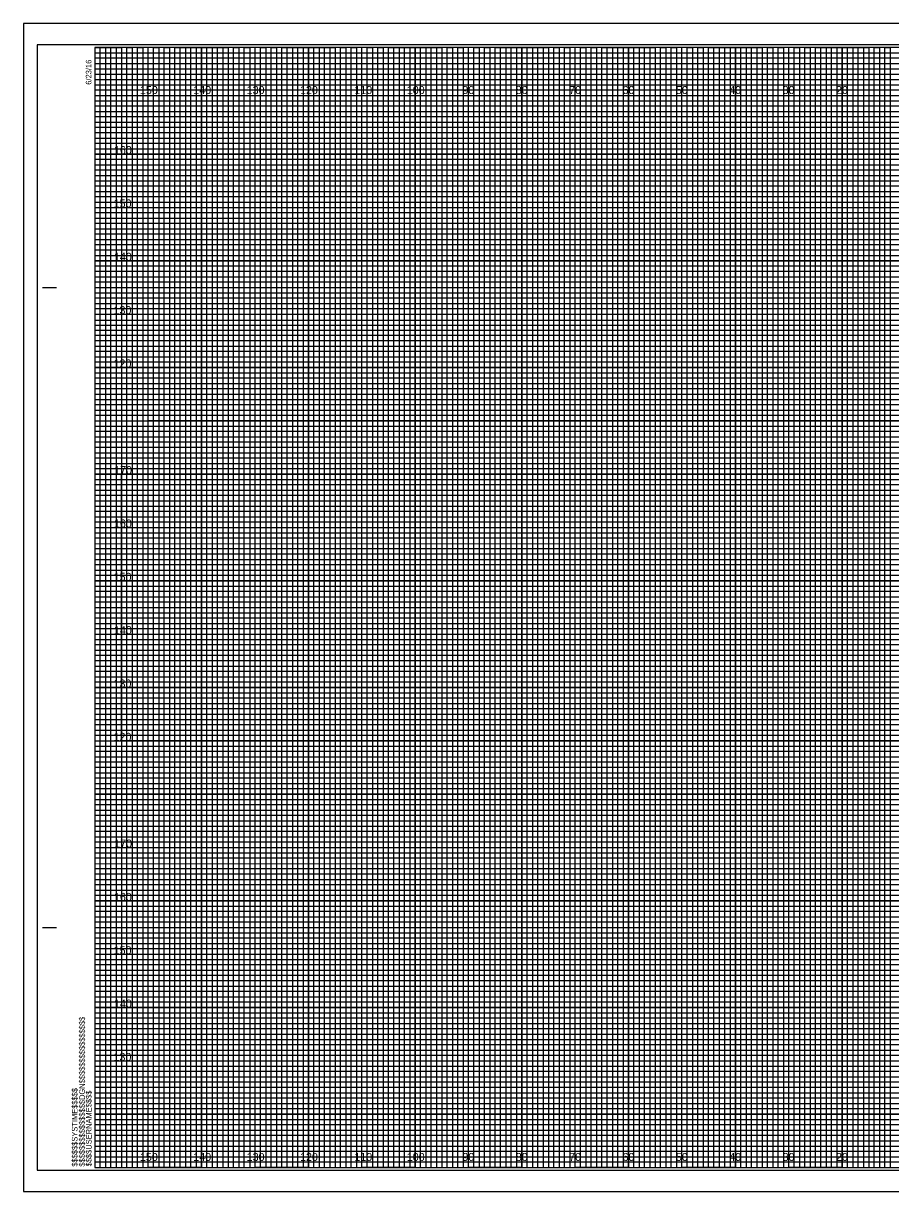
# Model space of a CAD drawing. Extents: x -13 to 323, y -5 to 3294.
# Drawn here: x -13.4 to 149.1, y 2415.5 to 2634.5 of the extents above; entities that cross this region are included whole.
import ezdxf

# ---------------------------------------------------------------- set-up
doc = ezdxf.new("R2010")
doc.units = 0
for name, color, linetype in [('Prop XS Elevation Labels', 7, 'Continuous'), ('Prop XS Offset Labels', 7, 'Continuous'), ('Scratch_Level_0', 7, 'Continuous'), ('Sheet Cross Section CELL', 7, 'Continuous'), ('Sheet Cross Section Grid Major CELL', 7, 'Continuous'), ('Sheet Cross Section Grid Middle CELL', 7, 'Continuous'), ('Sheet Cross Section Grid Minor 1 CELL', 7, 'Continuous'), ('Sheet Cross Section Grid Minor 2 CELL', 7, 'Continuous'), ('Sheet Cutting Line CELL', 7, 'Continuous'), ('Sheet DOT Grid CELL', 7, 'Continuous'), ('Sheet Plot Border Inside CELL', 7, 'Continuous'), ('Sheet Plot Border Outside CELL', 7, 'Continuous')]:
    doc.layers.add(name, color=color, linetype=linetype)

msp = doc.modelspace()

# ---------------------------------------------------------------- linework, layer by layer
at = {"layer": 'Scratch_Level_0'}
for points in [[(10, 2610), (310, 2610), (310, 2560), (10, 2560)], [(5, 2550), (310, 2550), (310, 2500), (5, 2500)], [(10, 2480), (310, 2480), (310, 2430), (10, 2430)]]:
    msp.add_lwpolyline(points, close=True, dxfattribs=at)
at = {"layer": 'Sheet Cross Section CELL'}
for p, q in [((-9.8, 2585), (-7.3, 2585)), ((-9.7, 2585), (-7.2, 2585)), ((-9.8, 2465), (-7.3, 2465)), ((-9.7, 2465), (-7.2, 2465)), ((0, 2420), (0, 2420)), ((0, 2420), (0, 2420)), ((0, 2420), (0, 2420)), ((0, 2420), (0, 2420)), ((0, 2420), (0, 2420)), ((0, 2420), (0, 2420)), ((0, 2420), (0, 2420))]:
    msp.add_line(p, q, dxfattribs=at)
msp.add_lwpolyline([(320, 2630), (0, 2630), (0, 2420), (320, 2420)], close=True, dxfattribs=at)
at = {"layer": 'Sheet Cross Section Grid Major CELL'}
for p, q in [((10, 2630), (0, 2630)), ((10, 2420), (10, 2630)), ((30, 2630), (20, 2630)), ((20, 2630), (20, 2420)), ((30, 2420), (30, 2630)), ((50, 2630), (40, 2630)), ((40, 2630), (40, 2420)), ((50, 2420), (50, 2630)), ((70, 2630), (60, 2630)), ((60, 2630), (60, 2420)), ((70, 2420), (70, 2630)), ((90, 2630), (80, 2630)), ((80, 2630), (80, 2420)), ((90, 2420), (90, 2630)), ((110, 2630), (100, 2630)), ((100, 2630), (100, 2420)), ((110, 2420), (110, 2630)), ((130, 2630), (120, 2630)), ((120, 2630), (120, 2420)), ((130, 2420), (130, 2630)), ((150, 2630), (140, 2630)), ((140, 2630), (140, 2420)), ((20, 2420), (10, 2420)), ((40, 2420), (30, 2420)), ((60, 2420), (50, 2420)), ((80, 2420), (70, 2420)), ((100, 2420), (90, 2420)), ((120, 2420), (110, 2420)), ((140, 2420), (130, 2420))]:
    msp.add_line(p, q, dxfattribs=at)
for points in [[(0, 2620), (320, 2620), (320, 2610), (0, 2610)], [(0, 2600), (320, 2600), (320, 2590), (0, 2590)], [(0, 2580), (320, 2580), (320, 2570), (0, 2570)], [(0, 2560), (320, 2560), (320, 2550), (0, 2550)], [(0, 2540), (320, 2540), (320, 2530), (0, 2530)], [(0, 2520), (320, 2520), (320, 2510), (0, 2510)], [(0, 2500), (320, 2500), (320, 2490), (0, 2490)], [(0, 2480), (320, 2480), (320, 2470), (0, 2470)], [(0, 2460), (320, 2460), (320, 2450), (0, 2450)], [(0, 2440), (320, 2440), (320, 2430), (0, 2430)]]:
    msp.add_lwpolyline(points, dxfattribs=at)
at = {"layer": 'Sheet Cross Section Grid Middle CELL'}
for points in [[(0, 2630), (5, 2630), (5, 2420), (15, 2420), (15, 2630), (25, 2630), (25, 2420), (35, 2420), (35, 2630), (45, 2630), (45, 2420), (55, 2420), (55, 2630), (65, 2630), (65, 2420), (75, 2420), (75, 2630), (85, 2630), (85, 2420), (95, 2420), (95, 2630), (105, 2630), (105, 2420), (115, 2420), (115, 2630), (125, 2630), (125, 2420), (135, 2420), (135, 2630), (145, 2630), (145, 2420), (155, 2420)], [(0, 2625), (275, 2625)], [(0, 2605), (320, 2605), (320, 2615), (0, 2615)], [(0, 2585), (320, 2585), (320, 2595), (0, 2595)], [(0, 2565), (320, 2565), (320, 2575), (0, 2575)], [(0, 2545), (320, 2545), (320, 2555), (0, 2555)], [(0, 2525), (320, 2525), (320, 2535), (0, 2535)], [(0, 2505), (320, 2505), (320, 2515), (0, 2515)], [(0, 2485), (320, 2485), (320, 2495), (0, 2495)], [(0, 2465), (320, 2465), (320, 2475), (0, 2475)], [(0, 2445), (320, 2445), (320, 2455), (0, 2455)], [(0, 2425), (320, 2425), (320, 2435), (0, 2435)]]:
    msp.add_lwpolyline(points, dxfattribs=at)
at = {"layer": 'Sheet Cross Section Grid Minor 1 CELL'}
for p, q in [((0, 2629), (260, 2629)), ((260, 2627.98), (0, 2627.98)), ((0, 2627.98), (0, 2627)), ((0, 2627), (260, 2627)), ((260, 2625.89), (0, 2625.89)), ((0, 2625.89), (0, 2624)), ((0, 2624), (320, 2624))]:
    msp.add_line(p, q, dxfattribs=at)
for points in [[(0, 2623), (270, 2623), (320, 2623), (320, 2622), (0, 2622)], [(0, 2621), (320, 2621), (320, 2619), (0, 2619)], [(0, 2618), (320, 2618), (320, 2617), (0, 2616.98)], [(0, 2616), (320, 2616), (320, 2614), (0, 2614)], [(0, 2613), (320, 2613), (320, 2612), (0, 2612)], [(0, 2611), (320, 2611), (320, 2609), (0, 2609)], [(0, 2608), (320, 2608), (320, 2607), (0, 2607)], [(0, 2606), (320, 2606), (320, 2604), (0, 2604)], [(0, 2603), (320, 2603), (320, 2602), (0, 2602)], [(0, 2601), (320, 2601), (320, 2599), (0, 2599)], [(0, 2598), (320, 2598), (320, 2597), (0, 2597)], [(0, 2596), (320, 2596), (320, 2593.95), (320, 2593), (320, 2592), (0, 2592)], [(0, 2594), (320, 2594), (320, 2593), (0, 2593)], [(0, 2591), (320, 2591), (320, 2589), (0, 2589.03)], [(0, 2589.03), (320, 2589), (320, 2588), (0, 2588)], [(0, 2587), (320, 2587), (320, 2586), (0, 2586)], [(0, 2584), (320, 2584), (320, 2583), (0, 2583)], [(0, 2582), (320, 2582), (320, 2581), (0, 2581)], [(-0.07, 2578.89), (320, 2578.89), (320, 2577.88), (-0.07, 2577.88)], [(0, 2577), (320, 2577), (320, 2576), (0, 2576)], [(0, 2574), (320, 2574), (320, 2573), (0, 2573)], [(0, 2572), (320, 2572), (320, 2571), (0, 2571)], [(0, 2569), (320, 2569), (320, 2568), (0, 2568)], [(0, 2567), (320, 2567), (320, 2566), (0, 2566)], [(0, 2564), (320, 2564), (320, 2563), (0, 2563)], [(0, 2562), (320, 2562), (320, 2561), (0, 2561)], [(0, 2559), (320, 2559), (319.99, 2557.98), (0, 2558)], [(0, 2557), (320, 2557), (320, 2556), (0, 2556)], [(0, 2554), (320, 2554), (320, 2553), (0, 2553)], [(0, 2552), (320, 2552), (320, 2551), (0, 2551)], [(0, 2549), (320, 2549), (320, 2548), (0, 2548)], [(0, 2547), (320, 2547), (320, 2546), (0, 2546)], [(0, 2544), (320, 2544), (320, 2543), (0, 2543)], [(0, 2542), (320, 2542), (320, 2541), (0, 2541)], [(0, 2539), (320, 2539), (320, 2538), (0, 2538)], [(0, 2536.99), (320.07, 2536.91), (320, 2536), (0, 2536)], [(0, 2534), (320, 2534), (320, 2533), (0, 2533)], [(0, 2532), (320, 2532), (320, 2531), (0, 2531)], [(0, 2529), (320, 2529), (320, 2528), (0, 2528)], [(0, 2527), (320, 2527), (320, 2526), (0, 2526)], [(0, 2524), (320, 2524), (320, 2523), (0, 2523)], [(0, 2522), (320, 2522), (320, 2521), (0, 2521)], [(0, 2519), (320, 2519), (320, 2518), (0, 2518)], [(0, 2517), (320, 2517), (320, 2516), (0, 2516)], [(0, 2514), (320, 2514), (320, 2513), (0, 2513)], [(0, 2512), (320, 2512), (320, 2511), (0, 2511)], [(0, 2509), (320, 2509), (320, 2508), (0, 2508)], [(0, 2507), (320, 2507), (320, 2506), (0, 2506)], [(0, 2504), (320, 2504), (320, 2503), (0, 2503)], [(0, 2502), (320, 2502), (320, 2501), (0, 2501)], [(0, 2499), (320, 2499), (319.99, 2497.98), (0, 2498)], [(0, 2497), (320, 2497), (320, 2496), (0, 2496)], [(0, 2494), (320, 2494), (320, 2493), (0, 2493)], [(0, 2492), (320, 2492), (320, 2491), (0, 2491)], [(0, 2489), (320, 2489), (320, 2488), (0, 2488)], [(0, 2487), (320, 2487), (320, 2486), (0, 2486)], [(0, 2484), (320, 2484), (320, 2483), (0, 2483)], [(0, 2482), (320, 2482), (320, 2481), (0, 2481)], [(0, 2479), (320, 2479), (320, 2478), (0, 2478)], [(0, 2476.99), (320.07, 2476.91), (320, 2476), (0, 2476)], [(0, 2474), (320, 2474), (320, 2473), (0, 2473)], [(0, 2472), (320, 2472), (320, 2471), (0, 2471)], [(0, 2469), (320, 2469), (320, 2468), (0, 2468)], [(0, 2467), (320, 2467), (320, 2466), (0, 2466)], [(0, 2464), (320, 2464), (320, 2463), (0, 2463)], [(0, 2462), (320, 2462), (320, 2461), (0, 2461)], [(0, 2459), (320, 2459), (320, 2458), (0, 2458)], [(0, 2457), (320, 2457), (320, 2456), (0, 2456)], [(0, 2454), (320, 2454), (320, 2453), (0, 2453)], [(0, 2452), (320, 2452), (320, 2451), (0, 2451)], [(0, 2449), (320, 2449), (320, 2448), (0, 2448)], [(0, 2447), (320, 2447), (320, 2446), (0, 2446)], [(0, 2444), (320, 2444), (320, 2443), (0, 2443)], [(0, 2442), (320, 2442), (320, 2441), (0, 2441)], [(0, 2439), (320, 2439), (320, 2438), (0, 2438)], [(0, 2437), (320, 2437), (320, 2436), (0, 2436)], [(0, 2434), (320, 2434), (320, 2433), (0, 2433)], [(0, 2432), (320, 2432), (320, 2431), (0, 2431)], [(0, 2429), (320, 2429), (320, 2428), (0, 2428)], [(0, 2427), (320, 2427), (320, 2426), (0, 2426)], [(0, 2424), (320, 2424), (320, 2423), (0, 2423)], [(0, 2422), (320, 2422), (320, 2421), (0, 2421)]]:
    msp.add_lwpolyline(points, dxfattribs=at)
at = {"layer": 'Sheet Cross Section Grid Minor 2 CELL'}
for points in [[(0, 2420), (1, 2420), (1, 2630), (2, 2630), (2, 2420)], [(2, 2420), (3, 2420), (3, 2630), (4, 2630), (4, 2420)], [(5, 2420), (6, 2420), (6, 2630), (7, 2630), (7, 2420)], [(7, 2420), (8, 2420), (8, 2630), (9, 2630), (9, 2420)], [(10, 2420), (11, 2420), (11, 2630), (12, 2630), (12, 2420)], [(12, 2420), (13, 2420), (13, 2630), (14, 2630), (14, 2420)], [(15, 2420), (16, 2420), (16, 2630), (17, 2630), (17, 2420)], [(17, 2420), (18, 2420), (18, 2630), (19, 2630), (19, 2420)], [(20, 2420), (21, 2420), (21, 2630), (22, 2630), (22, 2420)], [(22, 2420), (23, 2420), (23, 2630), (24, 2630), (24, 2420)], [(25, 2420), (26, 2420), (26, 2630), (27, 2630), (27, 2420)], [(27, 2420), (28, 2420), (28, 2630), (29, 2630), (29, 2420)], [(30, 2420), (31, 2420), (31, 2630), (32, 2630), (32, 2420)], [(32, 2420), (33, 2420), (33, 2630), (34, 2630), (34, 2420)], [(35, 2420), (36, 2420), (36, 2630), (37, 2630), (37, 2420)], [(37, 2420), (38, 2420), (38, 2630), (39, 2630), (39, 2420)], [(40, 2420), (41, 2420), (41, 2630), (42, 2630), (42, 2420)], [(42, 2420), (43, 2420), (43, 2630), (44, 2630), (44, 2420)], [(45, 2420), (46, 2420), (46, 2630), (47, 2630), (47, 2420)], [(47, 2420), (48, 2420), (48, 2630), (49, 2630), (49, 2420)], [(50, 2420), (51, 2420), (51, 2630), (52, 2630), (52, 2420)], [(52, 2420), (53, 2420), (53, 2630), (54, 2630), (54, 2420)], [(55, 2420), (56, 2420), (56, 2630), (57, 2630), (57, 2420)], [(57, 2420), (58, 2420), (58, 2630), (59, 2630), (59, 2420)], [(60, 2420), (61, 2420), (61, 2630), (62, 2630), (62, 2420)], [(62, 2420), (63, 2420), (63, 2630), (64, 2630), (64, 2420)], [(65, 2420), (66, 2420), (66, 2630), (67, 2630), (67, 2420)], [(67, 2420), (68, 2420), (68, 2630), (69, 2630), (69, 2420)], [(70, 2420), (71, 2420), (71, 2630), (72, 2630), (72, 2420)], [(72, 2420), (73, 2420), (73, 2630), (74, 2630), (74, 2420)], [(75, 2420), (76, 2420), (76, 2630), (77, 2630), (77, 2420)], [(77, 2420), (78, 2420), (78, 2630), (79, 2630), (79, 2420)], [(80, 2420), (81, 2420), (81, 2630), (82, 2630), (82, 2420)], [(82, 2420), (83, 2420), (83, 2630), (84, 2630), (84, 2420)], [(85, 2420), (86, 2420), (86, 2630), (87, 2630), (87, 2420)], [(87, 2420), (88, 2420), (88, 2630), (89, 2630), (89, 2420)], [(90, 2420), (91, 2420), (91, 2630), (92, 2630), (92, 2420)], [(92, 2420), (93, 2420), (93, 2630), (94, 2630), (94, 2420)], [(95, 2420), (96, 2420), (96, 2630), (97, 2630), (97, 2420)], [(97, 2420), (98, 2420), (98, 2630), (99, 2630), (99, 2420)], [(100, 2420), (101, 2420), (101, 2630), (102, 2630), (102, 2420)], [(102, 2420), (103, 2420), (103, 2630), (104, 2630), (104, 2420)], [(105, 2420), (106, 2420), (106, 2630), (107, 2630), (107, 2420)], [(107, 2420), (108, 2420), (108, 2630), (109, 2630), (109, 2420)], [(110, 2420), (111, 2420), (111, 2630), (112, 2630), (112, 2420)], [(112, 2420), (113, 2420), (113, 2630), (114, 2630), (114, 2420)], [(115, 2420), (116, 2420), (116, 2630), (117, 2630), (117, 2420)], [(117, 2420), (118, 2420), (118, 2630), (119, 2630), (119, 2420)], [(120, 2420), (121, 2420), (121, 2630), (122, 2630), (122, 2420)], [(122, 2420), (123, 2420), (123, 2630), (124, 2630), (124, 2420)], [(125, 2420), (126, 2420), (126, 2630), (127, 2630), (127, 2420)], [(127, 2420), (128, 2420), (128, 2630), (129, 2630), (129, 2420)], [(130, 2420), (131, 2420), (131, 2630), (132, 2630), (132, 2420)], [(132, 2420), (133, 2420), (133, 2630), (134, 2630), (134, 2420)], [(135, 2420), (136, 2420), (136, 2630), (137, 2630), (137, 2420)], [(137, 2420), (138, 2420), (138, 2630), (139, 2630), (139, 2420)], [(140, 2420), (141, 2420), (141, 2630), (142, 2630), (142, 2420)], [(142, 2420), (143, 2420), (143, 2630), (144, 2630), (144, 2420)], [(145, 2420), (146, 2420), (146, 2630), (147, 2630), (147, 2420)], [(147, 2420), (148, 2420), (148, 2630), (149, 2630), (149, 2420)]]:
    msp.add_lwpolyline(points, dxfattribs=at)
at = {"layer": 'Sheet Cutting Line CELL'}
for p, q in [((323.3, 2634.5), (-13.4, 2634.5)), ((-13.4, 2634.5), (-13.4, 2415.5)), ((-13.4, 2415.5), (323.3, 2415.5))]:
    msp.add_line(p, q, dxfattribs=at)
at = {"layer": 'Sheet DOT Grid CELL'}
for p, q in [((10, 2420), (10, 2630)), ((20, 2420), (20, 2630)), ((30, 2420), (30, 2630)), ((40, 2420), (40, 2630)), ((50, 2420), (50, 2630)), ((60, 2420), (60, 2630)), ((70, 2420), (70, 2630)), ((80, 2420), (80, 2630)), ((90, 2420), (90, 2630)), ((100, 2420), (100, 2630)), ((110, 2420), (110, 2630)), ((120, 2420), (120, 2630)), ((130, 2420), (130, 2630)), ((140, 2420), (140, 2630)), ((0, 2620), (320, 2620)), ((0, 2610), (320, 2610)), ((0, 2600), (320, 2600)), ((0, 2590), (320, 2590)), ((0, 2580), (320, 2580)), ((0, 2570), (320, 2570)), ((0, 2560), (320, 2560)), ((0, 2550), (320, 2550)), ((0, 2540), (320, 2540)), ((0, 2530), (320, 2530)), ((0, 2520), (320, 2520)), ((0, 2510), (320, 2510)), ((0, 2500), (320, 2500)), ((0, 2490), (320, 2490)), ((0, 2480), (320, 2480)), ((0, 2470), (320, 2470)), ((0, 2460), (320, 2460)), ((0, 2450), (320, 2450)), ((0, 2440), (320, 2440)), ((0, 2430), (320, 2430))]:
    msp.add_line(p, q, dxfattribs=at)
at = {"layer": 'Sheet Plot Border Inside CELL'}
msp.add_lwpolyline([(-10.8, 2419.5), (322.4, 2419.5), (322.4, 2630.5), (-10.8, 2630.5)], close=True, dxfattribs=at)
at = {"layer": 'Sheet Plot Border Outside CELL'}
msp.add_lwpolyline([(-13.4, 2415.5), (323.3, 2415.5), (323.3, 2634.5), (-13.4, 2634.5)], close=True, dxfattribs=at)

# ---------------------------------------------------------------- texts
at = {"layer": 'Prop XS Elevation Labels'}
for s, p in [('160', (3.57, 2610)), ('150', (3.52, 2600)), ('140', (3.57, 2590)), ('130', (3.49, 2580)), ('120', (3.5, 2570)), ('170', (3.61, 2550)), ('160', (3.57, 2540)), ('150', (3.52, 2530)), ('140', (3.57, 2520)), ('130', (3.49, 2510)), ('120', (3.5, 2500)), ('170', (3.61, 2480)), ('160', (3.57, 2470)), ('150', (3.52, 2460)), ('140', (3.57, 2450)), ('130', (3.49, 2440))]:
    msp.add_text(s, height=1.5, dxfattribs=at).set_placement(p)
at = {"layer": 'Prop XS Offset Labels'}
for s, p in [('150', (8.44, 2621.25)), ('140', (18.44, 2621.25)), ('130', (28.44, 2621.25)), ('120', (38.44, 2621.25)), ('110', (48.62, 2621.25)), ('100', (58.44, 2621.25)), ('90', (68.86, 2621.25)), ('80', (78.86, 2621.25)), ('70', (88.86, 2621.25)), ('60', (98.86, 2621.25)), ('50', (108.86, 2621.25)), ('40', (118.86, 2621.25)), ('30', (128.86, 2621.25)), ('20', (138.86, 2621.25)), ('150', (8.44, 2421.25)), ('140', (18.44, 2421.25)), ('130', (28.44, 2421.25)), ('120', (38.44, 2421.25)), ('110', (48.62, 2421.25)), ('100', (58.44, 2421.25)), ('90', (68.86, 2421.25)), ('80', (78.86, 2421.25)), ('70', (88.86, 2421.25)), ('60', (98.86, 2421.25)), ('50', (108.86, 2421.25)), ('40', (118.86, 2421.25)), ('30', (128.86, 2421.25)), ('20', (138.86, 2421.25))]:
    msp.add_text(s, height=1.5, dxfattribs=at).set_placement(p)
at = {"layer": 'Sheet Cross Section CELL'}
for s, p in [('6/23/16', (-0.65, 2623)), ('$$$$$$$$$$$$$$$$DGN$$$$$$$$$$$$$$$$', (-1.88, 2420.18)), ('$$$$$$SYSTIME$$$$$', (-3.26, 2420.18)), ('$$$$USERNAME$$$$', (-0.62, 2420.23))]:
    msp.add_text(s, height=1.05, rotation=90, dxfattribs=at).set_placement(p)

doc.saveas('drawing.dxf')
